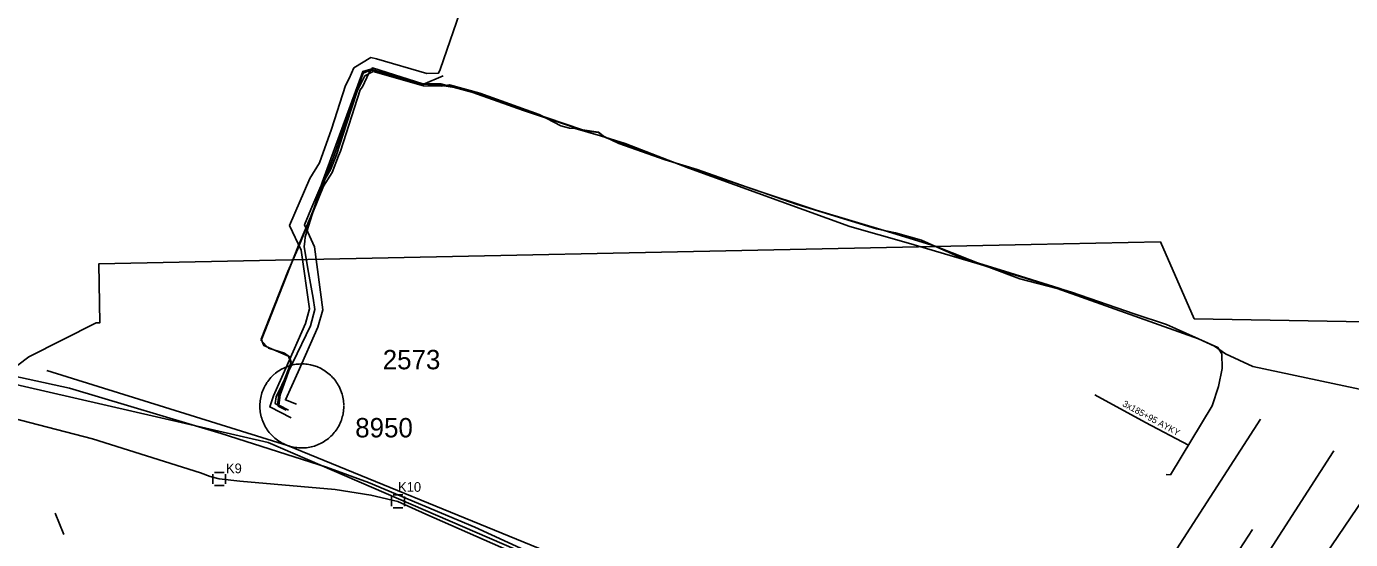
# Model space of a CAD drawing. Extents: x -748507 to -687366, y -1057342 to -1024924.
# Drawn here: x -736995.8 to -736790.7, y -1042263.6 to -1042184.2 of the extents above; entities that cross this region are included whole.
import ezdxf

# ---------------------------------------------------------------- set-up
doc = ezdxf.new("R2010")
doc.units = 0
for name, color, linetype in [('3xDOK_Pha Libeň - Holešovice', 7, 'Continuous'), ('DK - PHA - KOLÍN - ČD TELEMATIKA', 7, 'Continuous'), ('Kanalizace - pražské vodovody a kanalizace', 7, 'Continuous'), ('PRE - NN', 7, 'Continuous'), ('PRE - OK', 7, 'Continuous'), ('PRE - VN', 7, 'Continuous'), ('Telefonica O2', 7, 'Continuous'), ('TK+DOK_Pha Libeň - Běchovice', 7, 'Continuous'), ('Vodovod - přežsko vodovody a kanalizace', 7, 'Continuous')]:
    doc.layers.add(name, color=color, linetype=linetype)

msp = doc.modelspace()

# ---------------------------------------------------------------- linework, layer by layer
at = {"layer": '3xDOK_Pha Libeň - Holešovice'}
msp.add_lwpolyline([(-737007.19, -1042236.21), (-736989.11, -1042240.15), (-736965.65, -1042247.14), (-736949.3, -1042252.35), (-736942.79, -1042254.74), (-736926.34, -1042261.64), (-736901.88, -1042272.88), (-736873.32, -1042286.89), (-736862.27, -1042291.92), (-736855.04, -1042292.38), (-736853.51, -1042290.53), (-736851.39, -1042288.44), (-736848.5, -1042290.12), (-736845.53, -1042291.9), (-736843.78, -1042292.94), (-736840.05, -1042293.3), (-736837.47, -1042295.84), (-736854.45, -1042319.28), (-736868.54, -1042334.22), (-736879.19, -1042343.99), (-736902.89, -1042361.22)], dxfattribs=at)
at = {"layer": 'DK - PHA - KOLÍN - ČD TELEMATIKA'}
msp.add_line((-736989.99, -1042262.8), (-736991.33, -1042259.46), dxfattribs=at)
msp.add_lwpolyline([(-736817.05, -1042313.5), (-736820.86, -1042308.94), (-736879.81, -1042280.29), (-736916.51, -1042264.92), (-736955.37, -1042248.99), (-736992.65, -1042237.41)], dxfattribs=at)
at = {"layer": 'Kanalizace - pražské vodovody a kanalizace'}
msp.add_line((-736833.55, -1042304.58), (-736805.91, -1042262.02), dxfattribs=at)
at = {"layer": 'PRE - NN'}
for points in [[(-736955.19, -1042243.53), (-736956.72, -1042242.77), (-736956.52, -1042241.15), (-736955.48, -1042238.35), (-736954.78, -1042236.41), (-736955.2, -1042235.18), (-736959.01, -1042233.56), (-736959.42, -1042232.58), (-736955.3, -1042222.08), (-736953.75, -1042218.59), (-736951.38, -1042212.64), (-736948.09, -1042203.97), (-736943.65, -1042191.41), (-736942.85, -1042191.07), (-736942.18, -1042190.92), (-736934.53, -1042193.09), (-736931.7, -1042193.23), (-736928.24, -1042193.84), (-736918.82, -1042197.15), (-736912, -1042199.44), (-736909.7, -1042200.27), (-736907.18, -1042200.56), (-736906.43, -1042201.14), (-736904.07, -1042202.26), (-736896.85, -1042204.82), (-736891.91, -1042206.3), (-736883.46, -1042209.28), (-736873.46, -1042212.62), (-736862.43, -1042215.89), (-736854.89, -1042218.2), (-736847.2, -1042221.24), (-736844.3, -1042222.12), (-736833.95, -1042225.31), (-736824.23, -1042228.62), (-736819.25, -1042230.29), (-736811.25, -1042233.86), (-736810.66, -1042234.83), (-736810.6, -1042237.12), (-736811.17, -1042239.9), (-736812.15, -1042242.85), (-736818.61, -1042253.54), (-736819.29, -1042253.51)], [(-736830.3, -1042241.15), (-736822.46, -1042245.44), (-736815.81, -1042248.97)]]:
    msp.add_lwpolyline(points, dxfattribs=at)
at = {"layer": 'PRE - OK'}
for points in [[(-736954.81, -1042244.72), (-736958.1, -1042243.05), (-736957.53, -1042241.31), (-736955.63, -1042237.03), (-736952.56, -1042230.12), (-736951.93, -1042227.89), (-736953.26, -1042218.8), (-736955.03, -1042214.99), (-736951.9, -1042207.71), (-736950.42, -1042205.26), (-736948.55, -1042200.05), (-736946.39, -1042193.32), (-736945.8, -1042192.21), (-736945.1, -1042190.59), (-736942.47, -1042188.95), (-736941.58, -1042189.2), (-736933.76, -1042191.44), (-736931.95, -1042191.39), (-736931.69, -1042190.82), (-736931.19, -1042189.32), (-736926.15, -1042174.63)], [(-736688.44, -1042364.6), (-736798.99, -1042321.6), (-736806.43, -1042312.53), (-736828.54, -1042301.34), (-736843.58, -1042296.62), (-736850.9, -1042290.34), (-736854.18, -1042289.13), (-736867.55, -1042279.69), (-736870.07, -1042278.51), (-736874.29, -1042284.85), (-736875, -1042284.54), (-736895.89, -1042275.53), (-736958.36, -1042248.57), (-737013.45, -1042235.93), (-737029.95, -1042232.14), (-737034.93, -1042240.56), (-737138.5, -1042192.14)], [(-736953.95, -1042242.64), (-736955.68, -1042241.96), (-736953.73, -1042237.63), (-736950.66, -1042230.71), (-736949.89, -1042228.02), (-736951.19, -1042218.25), (-736952.72, -1042214.85), (-736951.73, -1042212.49), (-736950.19, -1042208.88), (-736948.7, -1042206.35), (-736947.79, -1042204.02), (-736946.2, -1042199.25), (-736944.58, -1042194.19), (-736944.04, -1042193.15), (-736943.4, -1042191.82), (-736942.1, -1042191.13), (-736934.28, -1042193.36), (-736931.53, -1042193.41), (-736930.25, -1042193.2), (-736925.55, -1042194.48), (-736916.38, -1042197.81), (-736913.01, -1042199.55), (-736911.68, -1042199.9), (-736910.83, -1042199.95), (-736906.88, -1042201.08), (-736903.05, -1042202.29), (-736893.21, -1042206.12), (-736868.28, -1042215.13), (-736859.18, -1042217.7), (-736847.18, -1042221.27), (-736841.92, -1042223.21), (-736836.14, -1042224.74), (-736820.38, -1042230.36), (-736814.26, -1042232.51), (-736811.79, -1042233.66), (-736810.09, -1042234.81), (-736805.86, -1042236.77), (-736779.39, -1042242.42)]]:
    msp.add_lwpolyline(points, dxfattribs=at)
at = {"layer": 'PRE - VN'}
for points in [[(-736828.39, -1042227.2), (-736832.93, -1042225.73), (-736835.91, -1042224.67), (-736843.49, -1042222.27), (-736849.01, -1042220.57), (-736851.61, -1042219.71), (-736854.62, -1042218.36), (-736857.19, -1042217.24), (-736861.22, -1042216.09), (-736864.16, -1042215.47), (-736876.43, -1042211.71), (-736883.11, -1042209.4), (-736893.06, -1042206.03), (-736895.65, -1042205.15), (-736897.45, -1042204.58), (-736904.03, -1042202.19), (-736906.19, -1042201.29), (-736907.18, -1042200.54), (-736909.67, -1042200.18), (-736918.04, -1042197.35), (-736924.52, -1042194.95), (-736931.62, -1042193.03), (-736934.38, -1042193.05), (-736942.18, -1042190.55), (-736942.75, -1042191.39), (-736943.76, -1042193.52), (-736944.08, -1042193.96), (-736947.14, -1042203.47), (-736947.47, -1042204.21), (-736948.42, -1042206.76), (-736949.79, -1042208.89), (-736951.46, -1042212.97), (-736951.93, -1042214.06), (-736953.76, -1042218.31), (-736959.44, -1042232.78), (-736958.32, -1042233.95), (-736955.81, -1042234.75), (-736955.04, -1042235.29), (-736954.79, -1042236.13), (-736956.7, -1042241.08), (-736956.86, -1042242.43), (-736956.81, -1042242.91), (-736955.55, -1042243.54)], [(-736956.62, -1042242.94), (-736957.25, -1042242.52), (-736957.11, -1042241.48), (-736954.52, -1042236.18), (-736951.79, -1042230.52), (-736951.11, -1042227.97), (-736951.39, -1042226.19), (-736952.2, -1042221.67), (-736952.79, -1042218.24), (-736952.69, -1042217.46), (-736952.6, -1042216.71), (-736950.01, -1042208.3), (-736943.7, -1042191.16), (-736942.45, -1042190.75), (-736934.41, -1042193.17), (-736931.25, -1042191.82)], [(-736951.79, -1042236.53), (-736950.83, -1042236.81)], [(-736947.26, -1042240.12), (-736946.9, -1042241.06)], [(-736946.7, -1042242.04), (-736946.64, -1042242.77)], [(-736946.64, -1042242.87), (-736946.71, -1042243.87)]]:
    msp.add_lwpolyline(points, dxfattribs=at)
for centre, radius, start, end in [((-736953.1, -1042242.93), 6.55, 122.1995, 130.9436), ((-736953.18, -1042242.83), 6.43, 113.2083, 122.1271), ((-736953.14, -1042242.89), 6.5, 104.5173, 113.332), ((-736953.14, -1042242.89), 6.5, 95.6894, 104.4994), ((-736953.13, -1042242.94), 6.55, 86.9437, 95.6941), ((-736953.15, -1042242.94), 6.55, 78.0889, 86.8356), ((-736953.14, -1042242.89), 6.5, 60.4132, 69.2273), ((-736953.14, -1042242.89), 6.5, 51.6184, 60.4285), ((-736953.14, -1042242.89), 6.5, 42.7819, 51.5983), ((-736953.14, -1042242.89), 6.5, 148.5655, 157.3812), ((-736953.14, -1042242.89), 6.5, 139.7542, 148.5705), ((-736953.14, -1042242.89), 6.5, 130.9569, 139.773), ((-736953.17, -1042242.92), 6.54, 34.0382, 42.7979), ((-736953.14, -1042242.89), 6.5, 25.1594, 33.9747), ((-736953.14, -1042242.89), 6.5, 166.2041, 175.0221), ((-736953.14, -1042242.89), 6.5, 157.3937, 166.208), ((-736953.14, -1042242.89), 6.5, 7.5567, 16.3683), ((-736953.14, -1042242.89), 6.5, 175.019, 183.834), ((-736953.14, -1042242.89), 6.5, 183.8315, 192.6398), ((-736953.14, -1042242.89), 6.5, 342.5169, 351.3305), ((-736953.14, -1042242.89), 6.5, 192.6494, 201.4633), ((-736953.14, -1042242.89), 6.5, 201.4647, 210.2805), ((-736953.17, -1042242.88), 6.53, 324.9158, 333.6879), ((-736953.14, -1042242.89), 6.5, 333.6732, 342.4898), ((-736953.14, -1042242.89), 6.5, 210.2811, 219.102), ((-736953.14, -1042242.89), 6.5, 219.0947, 227.9011), ((-736953.14, -1042242.89), 6.5, 227.9066, 236.7256), ((-736953.16, -1042242.86), 6.54, 298.4834, 307.2421), ((-736953.14, -1042242.89), 6.5, 307.2241, 316.043), ((-736953.11, -1042242.91), 6.46, 316.0136, 324.8748), ((-736953.12, -1042242.86), 6.53, 236.7654, 245.5376), ((-736953.15, -1042242.93), 6.46, 245.4779, 254.3501), ((-736953.14, -1042242.89), 6.5, 254.3381, 263.1545), ((-736953.14, -1042242.89), 6.5, 263.1835, 271.9968), ((-736953.14, -1042242.89), 6.5, 271.9701, 280.7863), ((-736953.14, -1042242.89), 6.5, 280.7977, 289.6119), ((-736953.14, -1042242.89), 6.5, 289.6166, 298.4364)]:
    msp.add_arc(centre, radius, start, end, dxfattribs=at)
at = {"layer": 'Telefonica O2'}
for points in [[(-736773.77, -1042230.11), (-736814.92, -1042229.4), (-736820.16, -1042217.51), (-736840.16, -1042217.92), (-736984.6, -1042220.91), (-736984.42, -1042230.02), (-736984.97, -1042230.03)], [(-736984.97, -1042230.03), (-736995.42, -1042235.31), (-737006.96, -1042244)], [(-737002.21, -1042388.32), (-736983.88, -1042386.26), (-736958.25, -1042382.24), (-736935.04, -1042375.8), (-736916.74, -1042368.21), (-736899.05, -1042358.05), (-736887.23, -1042349.85), (-736886.54, -1042351.2), (-736879.64, -1042364.74), (-736874.64, -1042361.16), (-736868.56, -1042356.09), (-736852.88, -1042342.26), (-736841.94, -1042331.33), (-736838.86, -1042327.83), (-736832.26, -1042320.33), (-736825.16, -1042310.6), (-736818.96, -1042301.8), (-736787.8, -1042255.9), (-736781.08, -1042246.8)]]:
    msp.add_lwpolyline(points, dxfattribs=at)
at = {"layer": 'TK+DOK_Pha Libeň - Běchovice'}
for p, q in [((-736966.94, -1042254.93), (-736966.94, -1042253.43)), ((-736966.69, -1042253.18), (-736965.19, -1042253.18)), ((-736964.94, -1042253.43), (-736964.94, -1042254.93)), ((-736965.19, -1042255.18), (-736966.69, -1042255.18)), ((-736939.25, -1042258.41), (-736939.25, -1042256.91)), ((-736939, -1042256.66), (-736937.5, -1042256.66)), ((-736937.25, -1042256.91), (-736937.25, -1042258.41)), ((-736937.5, -1042258.66), (-736939, -1042258.66))]:
    msp.add_line(p, q, dxfattribs=at)
msp.add_lwpolyline([(-737004.92, -1042242.96), (-736985.55, -1042247.96), (-736968.83, -1042253.24), (-736967.33, -1042253.8), (-736965.94, -1042254.18), (-736962.72, -1042254.52), (-736947.98, -1042255.83), (-736942.43, -1042256.68), (-736938.25, -1042257.66), (-736933.96, -1042259.65), (-736922.3, -1042264.77), (-736908.07, -1042271.1), (-736903.73, -1042273.18), (-736903.06, -1042273.48), (-736894.35, -1042277.62), (-736881.24, -1042282.56), (-736863.11, -1042290.47), (-736847.55, -1042297.81)], dxfattribs=at)
at = {"layer": 'Vodovod - přežsko vodovody a kanalizace'}
msp.add_line((-736837.2, -1042295.22), (-736804.65, -1042244.95), dxfattribs=at)
msp.add_lwpolyline([(-736838.07, -1042319.26), (-736793.4, -1042249.99), (-736793.32, -1042249.86)], dxfattribs=at)

# ---------------------------------------------------------------- texts
at = {"layer": 'PRE - NN'}
msp.add_text('3x185+95 AYKY', height=1, rotation=331.311, dxfattribs=at).set_placement((-736826.14, -1042242.85))
at = {"layer": 'PRE - VN'}
for s, p in [('2573', (-736940.61, -1042237.22)), ('8950', (-736944.87, -1042247.76))]:
    msp.add_text(s, height=3, dxfattribs=at).set_placement(p)
at = {"layer": 'TK+DOK_Pha Libeň - Běchovice'}
for s, p in [('K9', (-736964.89, -1042253.3)), ('K10', (-736938.24, -1042256.18))]:
    msp.add_text(s, height=1.5, dxfattribs=at).set_placement(p)

doc.saveas('drawing.dxf')
